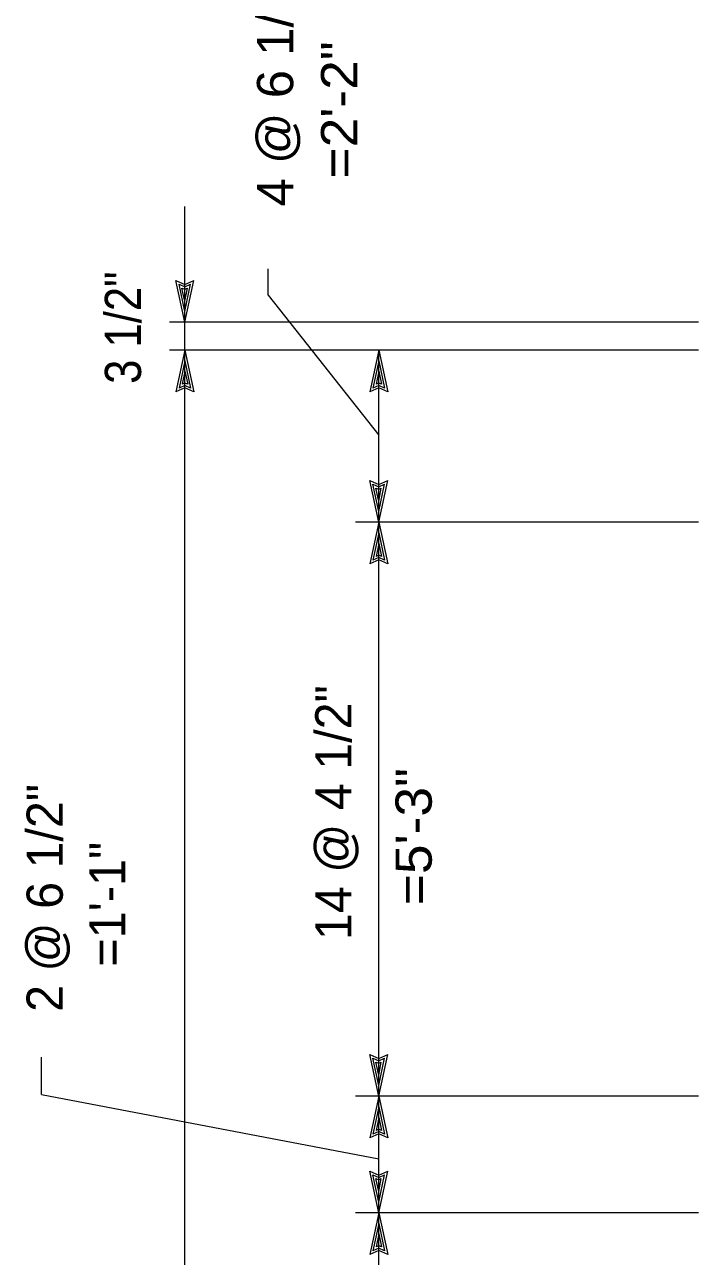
# Model space of a CAD drawing. Extents: x -28.1 to 13.9, y -16.1 to 13.9.
# Drawn here: x -4.681 to -2.356, y 7.352 to 11.603 of the extents above; entities that cross this region are included whole.
import ezdxf
from ezdxf.enums import TextEntityAlignment as Align

# ---------------------------------------------------------------- set-up
doc = ezdxf.new("R2010")
doc.units = 0
doc.header["$LTSCALE"] = 0.05
doc.layers.add('1', color=7, linetype='Continuous', lineweight=13)

msp = doc.modelspace()

# ---------------------------------------------------------------- linework, layer by layer
at = {"layer": '1'}
for p, q in [((-3.84004, 10.66869), (-3.84004, 10.75969)), ((-4.12804, 10.57569), (-4.15904, 10.71969)), ((-4.12804, 10.57569), (-4.09704, 10.71969)), ((-4.12804, 10.61269), (-4.14804, 10.70669)), ((-4.14804, 10.70669), (-4.12804, 10.69769)), ((-4.12804, 10.64869), (-4.13804, 10.69369)), ((-4.13804, 10.69369), (-4.12804, 10.68969)), ((-4.12804, 10.61269), (-4.10804, 10.70669)), ((-4.12804, 10.69769), (-4.10804, 10.70669)), ((-4.12804, 10.64869), (-4.11904, 10.69369)), ((-4.12804, 10.68969), (-4.11904, 10.69369)), ((-3.84004, 10.66869), (-3.45904, 10.18569)), ((-2.35604, 10.57569), (-4.18104, 10.57569)), ((-2.35604, 10.47969), (-4.18104, 10.47969)), ((-4.12804, 10.47969), (-4.15904, 10.33569)), ((-4.12804, 10.47969), (-4.09704, 10.33569)), ((-3.45904, 10.47969), (-3.49004, 10.33569)), ((-3.45904, 10.47969), (-3.42804, 10.33569)), ((-4.12804, 10.44269), (-4.14804, 10.34869)), ((-4.12804, 10.44269), (-4.10804, 10.34869)), ((-3.45904, 10.44269), (-3.47904, 10.34869)), ((-3.45904, 10.44269), (-3.43904, 10.34869)), ((-4.12804, 10.40669), (-4.13704, 10.36169)), ((-4.12804, 10.40669), (-4.11804, 10.36169)), ((-3.45904, 10.40669), (-3.46804, 10.36169)), ((-3.45904, 10.40669), (-3.44904, 10.36169)), ((-4.12804, 10.35769), (-4.14804, 10.34869)), ((-4.12804, 10.36569), (-4.13704, 10.36169)), ((-4.11804, 10.36169), (-4.12804, 10.36569)), ((-4.10804, 10.34869), (-4.12804, 10.35769)), ((-3.45904, 10.35769), (-3.47904, 10.34869)), ((-3.45904, 10.36569), (-3.46804, 10.36169)), ((-3.44904, 10.36169), (-3.45904, 10.36569)), ((-3.43904, 10.34869), (-3.45904, 10.35769)), ((-3.45904, 9.88569), (-3.49004, 10.02969)), ((-3.45904, 9.92269), (-3.47904, 10.01669)), ((-3.47904, 10.01669), (-3.45904, 10.00769)), ((-3.45904, 9.95869), (-3.46904, 10.00369)), ((-3.46904, 10.00369), (-3.45904, 9.99969)), ((-3.45904, 9.88569), (-3.42804, 10.02969)), ((-3.45904, 9.92269), (-3.43904, 10.01669)), ((-3.45904, 10.00769), (-3.43904, 10.01669)), ((-3.45904, 9.95869), (-3.45004, 10.00369)), ((-3.45904, 9.99969), (-3.45004, 10.00369)), ((-2.35604, 9.88569), (-3.53904, 9.88569)), ((-3.45904, 9.88569), (-3.49004, 9.74169)), ((-3.45904, 9.88569), (-3.42804, 9.74169)), ((-3.45904, 9.84869), (-3.47904, 9.75469)), ((-3.45904, 9.84869), (-3.43904, 9.75469)), ((-3.45904, 9.81269), (-3.46804, 9.76769)), ((-3.45904, 9.81269), (-3.44904, 9.76769)), ((-3.45904, 9.76369), (-3.47904, 9.75469)), ((-3.45904, 9.77169), (-3.46804, 9.76769)), ((-3.44904, 9.76769), (-3.45904, 9.77169)), ((-3.43904, 9.75469), (-3.45904, 9.76369)), ((-4.62204, 7.91069), (-4.62204, 8.03969)), ((-3.45904, 7.90469), (-3.49004, 8.04869)), ((-3.45904, 7.94169), (-3.47904, 8.03569)), ((-3.47904, 8.03569), (-3.45904, 8.02669)), ((-3.45904, 7.90469), (-3.42804, 8.04869)), ((-3.45904, 7.94169), (-3.43904, 8.03569)), ((-3.45904, 8.02669), (-3.43904, 8.03569)), ((-3.45904, 7.97769), (-3.46904, 8.02269)), ((-3.46904, 8.02269), (-3.45904, 8.01869)), ((-3.45904, 7.97769), (-3.45004, 8.02269)), ((-3.45904, 8.01869), (-3.45004, 8.02269)), ((-4.62204, 7.91069), (-3.45904, 7.68869)), ((-2.35604, 7.90469), (-3.53904, 7.90469)), ((-3.45904, 7.90469), (-3.49004, 7.76069)), ((-3.45904, 7.86769), (-3.47904, 7.77369)), ((-3.45904, 7.90469), (-3.42804, 7.76069)), ((-3.45904, 7.86769), (-3.43904, 7.77369)), ((-3.45904, 7.83169), (-3.46804, 7.78669)), ((-3.45904, 7.83169), (-3.44904, 7.78669)), ((-3.45904, 7.78269), (-3.47904, 7.77369)), ((-3.45904, 7.79069), (-3.46804, 7.78669)), ((-3.44904, 7.78669), (-3.45904, 7.79069)), ((-3.43904, 7.77369), (-3.45904, 7.78269)), ((-3.45904, 7.50269), (-3.49004, 7.64669)), ((-3.45904, 7.53969), (-3.47904, 7.63369)), ((-3.47904, 7.63369), (-3.45904, 7.62469)), ((-3.45904, 7.57569), (-3.46904, 7.62069)), ((-3.46904, 7.62069), (-3.45904, 7.61669)), ((-3.45904, 7.50269), (-3.42804, 7.64669)), ((-3.45904, 7.53969), (-3.43904, 7.63369)), ((-3.45904, 7.62469), (-3.43904, 7.63369)), ((-3.45904, 7.57569), (-3.45004, 7.62069)), ((-3.45904, 7.61669), (-3.45004, 7.62069)), ((-2.35604, 7.50269), (-3.53904, 7.50269)), ((-3.45904, 7.50269), (-3.49004, 7.35869)), ((-3.45904, 7.50269), (-3.42804, 7.35869)), ((-3.45904, 7.46569), (-3.47904, 7.37169)), ((-3.45904, 7.46569), (-3.43904, 7.37169)), ((-3.45904, 7.42969), (-3.46804, 7.38469)), ((-3.45904, 7.42969), (-3.44904, 7.38469)), ((-3.45904, 7.38069), (-3.47904, 7.37169)), ((-3.45904, 7.38869), (-3.46804, 7.38469)), ((-3.44904, 7.38469), (-3.45904, 7.38869)), ((-3.43904, 7.37169), (-3.45904, 7.38069))]:
    msp.add_line(p, q, dxfattribs=at)
for points in [[(-4.12804, 2.73469), (-4.12804, 3.07369), (-4.12804, 3.19769), (-4.12804, 10.47969), (-4.12804, 10.57569), (-4.12804, 10.97569)], [(-4.15904, 10.71969), (-4.12804, 10.70569), (-4.09704, 10.71969)], [(-3.45904, 3.19769), (-3.45904, 3.80669), (-3.45904, 5.20669), (-3.45904, 5.62469), (-3.45904, 7.50269), (-3.45904, 7.90469), (-3.45904, 9.88569), (-3.45904, 10.47969)], [(-4.09704, 10.33569), (-4.12804, 10.34969), (-4.15904, 10.33569)], [(-3.42804, 10.33569), (-3.45904, 10.34969), (-3.49004, 10.33569)], [(-3.49004, 10.02969), (-3.45904, 10.01569), (-3.42804, 10.02969)], [(-3.42804, 9.74169), (-3.45904, 9.75569), (-3.49004, 9.74169)], [(-3.49004, 8.04869), (-3.45904, 8.03469), (-3.42804, 8.04869)], [(-3.42804, 7.76069), (-3.45904, 7.77469), (-3.49004, 7.76069)], [(-3.49004, 7.64669), (-3.45904, 7.63269), (-3.42804, 7.64669)], [(-3.42804, 7.35869), (-3.45904, 7.37269), (-3.49004, 7.35869)]]:
    msp.add_lwpolyline(points, dxfattribs=at)

# ---------------------------------------------------------------- texts
at = {"layer": '1', "width": 1.05}
msp.add_text('4 @ 6 1/2"', height=0.125, rotation=90, dxfattribs=at).set_placement((-3.75404, 11.80144), align=Align.RIGHT)
at = {"layer": '1'}
for s, width, p in [('=2\'-2"', 1.1, (-3.53304, 11.30871)), ('3 1/2"', 0.9, (-4.27904, 10.55712)), ('=5\'-3"', 1.1, (-3.27604, 8.80071))]:
    msp.add_text(s, height=0.125, rotation=90, dxfattribs=dict(at, width=width)).set_placement(p, align=Align.CENTER)
for s, p in [('14 @ 4 1/2"', (-3.55304, 8.8834)), ('2 @ 6 1/2"', (-4.54904, 8.58915)), ('=1\'-1"', (-4.33304, 8.56757))]:
    msp.add_text(s, height=0.125, rotation=90, dxfattribs=at).set_placement(p, align=Align.CENTER)

doc.saveas('drawing.dxf')
